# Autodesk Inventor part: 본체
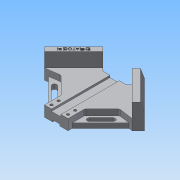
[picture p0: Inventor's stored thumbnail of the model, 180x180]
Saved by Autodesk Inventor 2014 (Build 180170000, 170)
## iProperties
Created: 2020-05
Part Number: 본체
Material: 알루미늄 6061
Document SubType Name: Modeling
Designer: net
Density: 2.71 g/cm^3
Appearance: 알루미늄 - 평지
Mass: 579.76 g
Surface Area: 409.973 cm^2
Volume: 213.934 cm^3
Author: net
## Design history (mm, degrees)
sketch "스케치1"
  geometry: L1 (0, 84.853)-(-84.853, 0); L2 (-84.853, 0)-(0, -84.853); L3 (0, -84.853)-(84.853, 0); L4 (84.853, 0)-(0, 84.853); L5 (-84.853, 0)-(84.853, 0); L6 (-35.355, 49.497)-(-20, 34.142); L7 (-20, 34.142)-(20, 34.142); L8 (20, 34.142)-(35.355, 49.497); L9 (0, 84.853)-(0, -84.853); L10 (-20, -64.853)-(20, -64.853); L11 (-6, 34.142)-(-6, -64.853); L12 (6, 34.142)-(6, -64.853); L13 (24.749, 38.891)-(74.246, -10.607); L14 (-24.749, 38.891)-(-74.246, -10.607); 4 further points
  constraints: 28 end point, 12 point on line, 9 perpendicular, 2 coincident, 2 midpoint, 2 parallel, 2 vertical alignment, 1 horizontal, 1 horizontal alignment
  dimensions: "d6" = 120 distance of L3.end L1.start; "d7" = 120 distance of L2.end L3.end (derived); "d8" = 40 distance of L6.end L7.end; "d9" = 50 distance of L1.start L6.start; "d10" = 50 distance of L8.end L1.start; "d11" = 20 distance from line of L2.end L10; "d13" = 12 distance between parallel lines of L12 L11; "d14" = 6 distance from line of L12 point (0, 0); "d15" = 15 distance between parallel lines of L4 L13; "d16" = 15 distance between parallel lines of L14 L1
extrude "돌출1" new body sketch "스케치1" distance "d17" = 42; taper "d18" = 0 deg
extrude "돌출2" join sketch "스케치1" distance "d19" = 18; taper "d20" = 0 deg
extrude "돌출4" cut sketch "스케치1" distance "d23" = 3; taper "d24" = 0 deg
sketch "스케치2"
  geometry: L1 (-20, -64.853)-(20, -64.853) reference; L2 (20, 34.142)-(-20, 34.142) reference; L3 (-8, 34.142)-(-8, -64.853); L4 (8, 34.142)-(8, -64.853); 1 further point
  constraints: 4 end point, 4 point on line, 2 perpendicular
  dimensions: "d25" = 16 distance between parallel lines of L4 L3; "d26" = 8 distance from line of L4 point (0, 0)
extrude "돌출5" cut sketch "스케치2" distance "d27" = 3.5; taper "d28" = 0 deg
sketch "스케치3"
  geometry: L1 (0, 42)-(0, 0) reference; L2 (15, 0)-(0, 0) reference; L3 (5, 0)-(0, 15); 1 further point
  constraints: 2 end point, 2 point on line
  dimensions: "d30" = 5 distance of L1.end L3.start; "d31" = 15 distance of L3.end L1.end
extrude "돌출6" cut sketch "스케치3" stored distance "d32" = 3.5; taper "d33" = 0 deg
sketch "스케치4"
  geometry: L1 (-74.246, -10.607)-(-20, -64.853) reference; L2 (-20, -64.853)-(-8, -64.853) reference; L3 (-74.246, -10.607)-(-49.497, -7.071); L4 (-49.497, -7.071)-(-20, -36.569); L5 (-20, -36.569)-(-20, -64.853); L6 (-84.853, 0)-(-35.355, 49.497) reference; L7 (-84.853, 0)-(-20, -64.853) reference; L8 (-49.497, -7.071)-(-63.64, -21.213); L9 (8, -64.853)-(-8, -64.853) reference; L10 (6, -64.853)-(20, -64.853) reference; 1 further point
  constraints: 8 end point, 2 perpendicular, 1 parallel, 1 point on line
  dimensions: "d34" = 20 distance between parallel lines of L4 L1; "d35" = 30 distance between parallel lines of L8 L6
extrude "돌출7" cut sketch "스케치4" stored distance "d36" = 10; taper "d37" = 0 deg
sketch "스케치5"
  geometry: L1 (-20, 34.142)-(-6, 34.142) reference; L2 (-6, 34.142)-(-6, -64.853) reference; L3 (-6, -64.853)-(-20, -64.853) reference; L4 (-20, -64.853)-(-20, -36.569) reference; L5 (-20, -36.569)-(-49.497, -7.071) reference; L6 (-49.497, -7.071)-(-74.246, -10.607) reference; L7 (-74.246, -10.607)-(-84.853, 0) reference; L8 (-84.853, 0)-(-35.355, 49.497) reference; L9 (-35.355, 49.497)-(-20, 34.142) reference; L10 (6, 34.142)-(20, 34.142) reference; L11 (20, 34.142)-(35.355, 49.497) reference; L12 (35.355, 49.497)-(84.853, 0) reference; L13 (84.853, 0)-(74.246, -10.607) reference; L14 (74.246, -10.607)-(49.497, -7.071) reference; L15 (49.497, -7.071)-(20, -36.569) reference; L16 (20, -36.569)-(20, -64.853) reference; L17 (20, -64.853)-(6, -64.853) reference; L18 (6, -64.853)-(6, 34.142) reference; L19 (-68.059, -9.723)-(-20, -57.782); L20 (-49.497, -18.385)-(-29.698, -38.184); L21 (-52.326, -21.213)-(-32.527, -41.012); L22 (-26.87, -35.355)-(-46.669, -15.556); L23 (-74.246, -10.607)-(-49.497, -7.071) reference; L24 (-49.497, -7.071)-(-20, -36.569) reference; L25 (-20, -36.569)-(-20, -64.853) reference; L26 (-68.059, -9.723)-(-49.497, -7.071); L27 (-20, -36.569)-(-20, -57.782); L28 (-20, -36.569)-(-49.497, -7.071); A1 r 4 centre (-49.497, -18.385) between (-46.669, -15.556) and (-52.326, -21.213); A2 r 4 centre (-29.698, -38.184) between (-32.527, -41.012) and (-26.87, -35.355); 2 further points
  constraints: 16 end point, 4 point on circle, 4 tangent, 3 collinear, 2 centre point, 2 parallel, 2 point on line, 1 midpoint, 1 perpendicular
  dimensions: "d38" = 5 distance between parallel lines of L19 L7; "d39" = 12 distance between parallel lines of L20 L7; "d40" = 8 distance between parallel lines of L22 L21; "d41" = 38 distance from line of L20.start L8; "d43" = 28 distance of L20.start L20.end
extrude "돌출8" join sketch "스케치5" distance "d44" = 8; taper "d45" = 0 deg
sketch "스케치6"
  geometry: L1 (-20, -36.569)-(-20, -64.853) reference; L2 (-20, -64.853)-(-8, -64.853) reference; C1 r 2.25 at (-14, -46.853); C2 r 2.25 at (-14, -58.853); 5 further points
  constraints: 2 centre point, 2 coincident, 2 horizontal alignment, 2 vertical alignment
  dimensions: "d46" = 12 distance of point (14, -58.853) point (14, -46.853); "d47" = 6 distance from line of L2 point (14, -58.853); "d48" = 28 distance of point (14, -58.853) point (-14, -58.853); "d49" = 6 distance from line of point (-14, -58.853) L1; "d50" = 4.5 diameter of C1; "d51" = 4.5 diameter of C2
extrude "돌출9" cut sketch "스케치6" distance "d52" = 8; taper "d53" = 0 deg
sketch "스케치7"
  geometry: L1 (20, -64.853)-(20, -57.782) reference; L2 (20, -64.853)-(6, -64.853) reference; C1 r 2.25 at (14, -58.853) reference; C2 r 4 at (14, -46.853); C3 r 4 at (14, -58.853); 5 further points
  constraints: 2 centre point, 2 coincident, 2 horizontal alignment, 2 vertical alignment
  dimensions: "d55" = 28 distance of point (14, -58.853) point (-14, -58.853); "d56" = 6 distance from line of L1 point (14, -58.853); "d57" = 6 distance from line of point (14, -58.853) L2; "d58" = 12 distance of point (14, -46.853) C1.centre; "d59" = 8 diameter of C2; "d60" = 8 diameter of C3
extrude "돌출10" cut sketch "스케치7" distance "d61" = 10; taper "d62" = 0 deg
sketch "스케치8"
  geometry: L1 (-74.246, -10.607)-(-24.749, 38.891) reference; L2 (-24.749, 38.891)-(-31.82, 45.962) reference; 2 further points
  constraints: 1 other
  dimensions: "d63" = 35 distance from line of L2 point (-53.033, 17.678); "d64" = 5 distance from line of L1 point (-53.033, 17.678)
feature "엠보싱1" sketch "스케치8" dims "d6" = 120, "d7" = 120 (derived), "d8" = 40, "d9" = 50, "d10" = 50, "d11" = 20, "d13" = 12, "d14" = 6, "d15" = 15, "d16" = 15, "d65" = 0.5, "d66" = 0
fillet "모깎기1" dims "d67" = 5
fillet "모깎기2" dims "d68" = 5
node "솔리드1"
mirror "대칭1"
mirror "대칭2"
mirror "대칭3"
mirror "대칭4"
node "작업 평면1"
node "절단 모서리 투영1"
